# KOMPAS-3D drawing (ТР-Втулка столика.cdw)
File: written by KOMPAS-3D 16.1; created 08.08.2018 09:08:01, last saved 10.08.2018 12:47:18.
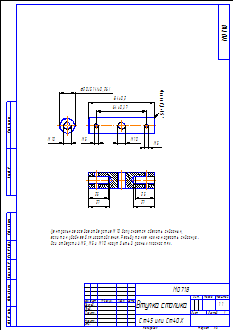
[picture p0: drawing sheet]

Sheet 1: A3, portrait

Title block, sheet 1: name: Втулка столика; designation: М0718; material: Ст45 или Ст40Х; scale: 1:1; sheets: 1; sheet format: A3; stored path: C:\Users\User\Desktop\Станки\Малый 0718\ТР-Втулка столика.cdw

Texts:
  User
  JS14( 0,26)
  Центральное осевое отверстие М10 допускается сделать сквозным,
  если так удобнее для изготовления. Резьбу также можно нарезать сквозную.
  Оси отверстий М5, М5 и М10 могут быть в разных плоскостях.
  Фаски 0,6 45
Dimensions and other numbers on the sheet: 10; 5; 84±0,2; 20; 25; 64±0,37; 27; 1:1; 1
